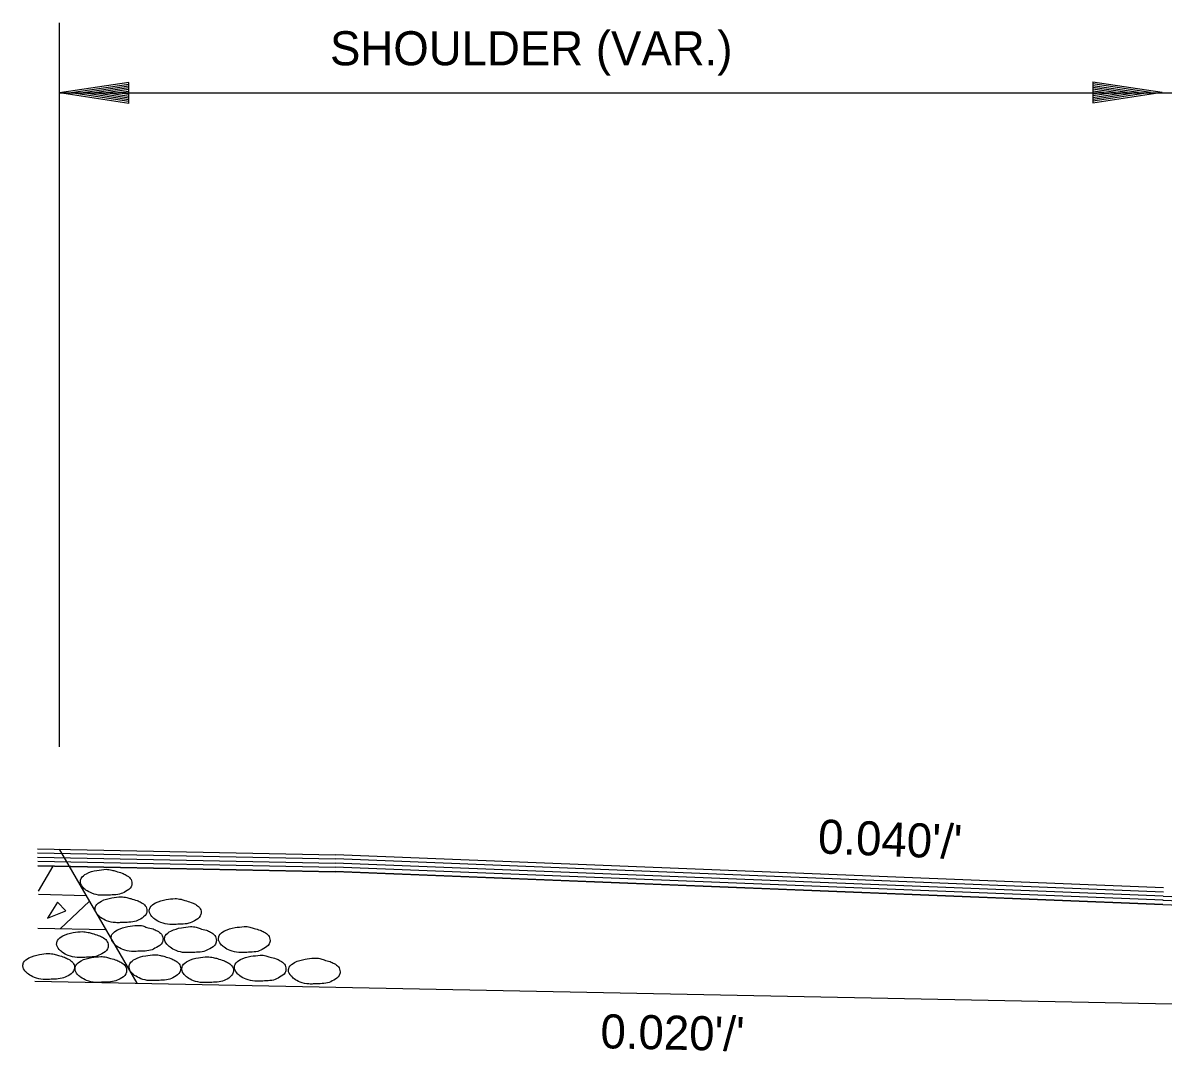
# Model space of a CAD drawing. Extents: x 1929624 to 1935547, y 596315 to 605721.
# Drawn here: x 1932754.9 to 1932958.2, y 604827.1 to 605010.5 of the extents above; entities that cross this region are included whole.
import ezdxf

# ---------------------------------------------------------------- set-up
doc = ezdxf.new("R2010")
doc.units = 0
doc.layers.add('Default', color=7, linetype='Continuous')

msp = doc.modelspace()

# ---------------------------------------------------------------- linework, layer by layer
at = {"layer": 'Default'}
for p, q in [((1932761.46, 604881.33), (1932761.46, 605010.47)), ((1932773.79, 604999.81), (1932761.46, 604997.97)), ((1932773.79, 604999.49), (1932763.53, 604997.97)), ((1932773.79, 604999.17), (1932765.65, 604997.97)), ((1932773.79, 604998.88), (1932767.71, 604997.97)), ((1932773.79, 604998.56), (1932769.78, 604997.97)), ((1932773.79, 604998.24), (1932771.85, 604997.97)), ((1932773.79, 604996.1), (1932773.79, 604999.81)), ((1932945.72, 604999.94), (1932958.05, 604998.07)), ((1932945.72, 604999.94), (1932945.72, 604996.22)), ((1932945.72, 604999.62), (1932955.98, 604998.07)), ((1932945.72, 604999.3), (1932953.87, 604998.07)), ((1932945.72, 604999), (1932951.8, 604998.07)), ((1932945.72, 604998.68), (1932949.73, 604998.07)), ((1932945.72, 604998.36), (1932947.67, 604998.07)), ((1932945.72, 604996.22), (1932958.05, 604998.07)), ((1932945.72, 604997.48), (1932949.73, 604998.07)), ((1932945.72, 604996.86), (1932953.87, 604998.07)), ((1932945.72, 604996.54), (1932955.98, 604998.07)), ((1932945.72, 604997.16), (1932951.8, 604998.07)), ((1932945.72, 604997.8), (1932947.67, 604998.07)), ((1932761.46, 604997.97), (1933091.99, 604997.97)), ((1932773.79, 604996.1), (1932761.46, 604997.97)), ((1932773.79, 604996.42), (1932763.53, 604997.97)), ((1932773.79, 604996.74), (1932765.65, 604997.97)), ((1932773.79, 604997.03), (1932767.71, 604997.97)), ((1932773.79, 604997.35), (1932769.78, 604997.97)), ((1932773.79, 604997.67), (1932771.85, 604997.97)), ((1932757.5, 604863.16), (1932810.67, 604862.11)), ((1932757.5, 604862.43), (1932810.67, 604861.37)), ((1932775.29, 604839.18), (1932761.46, 604863.08)), ((1932958.29, 604856.2), (1932810.67, 604862.11)), ((1932757.53, 604861.69), (1932810.67, 604860.63)), ((1932757.55, 604860.95), (1932810.67, 604859.89)), ((1932757.58, 604860.21), (1932810.62, 604859.15)), ((1932757.58, 604860.11), (1932810.67, 604859.06)), ((1932757.68, 604855.64), (1932760.33, 604860.09)), ((1932958.25, 604854.73), (1932810.62, 604860.63)), ((1932958.25, 604853.99), (1932810.62, 604859.89)), ((1932958.29, 604855.46), (1932810.67, 604861.37)), ((1932958.2, 604853.25), (1932810.57, 604859.15)), ((1932958.2, 604853.15), (1932810.67, 604859.06)), ((1932757.7, 604855.05), (1932766.21, 604854.87)), ((1932761.56, 604848.92), (1932766.8, 604853.86)), ((1932958.2, 604853.99), (1933092.85, 604848.6)), ((1932958.23, 604854.73), (1933092.89, 604849.34)), ((1932958.17, 604853.25), (1933092.83, 604847.86)), ((1932757.58, 604849), (1932769.75, 604848.75)), ((1932757.02, 604839.54), (1933150.4, 604831.72))]:
    msp.add_line(p, q, dxfattribs=at)
msp.add_lwpolyline([(1932759.31, 604850.78), (1932762.56, 604852.11), (1932761.08, 604853.68), (1932759.31, 604850.78)], dxfattribs=at)
for points in [[(1932769.74, 604859.51), (1932768.12, 604859.32), (1932766.25, 604858.73), (1932765.31, 604857.89), (1932765.16, 604857.3), (1932765.61, 604856.32), (1932766.15, 604855.82), (1932767.23, 604855.23), (1932768.8, 604854.89), (1932769.59, 604854.89), (1932770.82, 604854.94), (1932772.15, 604855.09), (1932773.23, 604855.53), (1932774.22, 604856.41), (1932774.37, 604857.01), (1932774.07, 604857.89), (1932773.33, 604858.48), (1932772.59, 604858.83), (1932771.51, 604859.17), (1932770.77, 604859.37), (1932769.74, 604859.51)], [(1932772.41, 604854.63), (1932770.79, 604854.43), (1932768.92, 604853.84), (1932767.94, 604853), (1932767.79, 604852.41), (1932768.23, 604851.43), (1932768.77, 604850.94), (1932769.85, 604850.35), (1932771.43, 604850), (1932772.27, 604850), (1932773.5, 604850.05), (1932774.82, 604850.2), (1932775.86, 604850.64), (1932776.89, 604851.53), (1932777.04, 604852.12), (1932776.74, 604853), (1932776.01, 604853.59), (1932775.27, 604853.94), (1932774.14, 604854.28), (1932773.45, 604854.48), (1932772.41, 604854.63)], [(1932782.07, 604854.31), (1932780.45, 604854.11), (1932778.58, 604853.52), (1932777.6, 604852.68), (1932777.45, 604852.09), (1932777.89, 604851.11), (1932778.43, 604850.62), (1932779.52, 604850.03), (1932781.09, 604849.68), (1932781.93, 604849.68), (1932783.16, 604849.73), (1932784.49, 604849.88), (1932785.52, 604850.32), (1932786.55, 604851.21), (1932786.7, 604851.8), (1932786.4, 604852.68), (1932785.67, 604853.27), (1932784.93, 604853.62), (1932783.8, 604853.96), (1932783.11, 604854.16), (1932782.07, 604854.31)], [(1932765.51, 604848.42), (1932763.88, 604848.22), (1932762.01, 604847.63), (1932761.08, 604846.79), (1932760.93, 604846.2), (1932761.37, 604845.22), (1932761.92, 604844.73), (1932763, 604844.14), (1932764.57, 604843.79), (1932765.36, 604843.79), (1932766.59, 604843.84), (1932767.92, 604843.99), (1932769, 604844.43), (1932769.99, 604845.32), (1932770.13, 604845.91), (1932769.84, 604846.79), (1932769.1, 604847.39), (1932768.36, 604847.73), (1932767.28, 604848.07), (1932766.54, 604848.27), (1932765.51, 604848.42)], [(1932775.28, 604849.51), (1932773.65, 604849.31), (1932771.78, 604848.72), (1932770.8, 604847.89), (1932770.65, 604847.34), (1932771.09, 604846.36), (1932771.63, 604845.82), (1932772.72, 604845.23), (1932774.29, 604844.88), (1932775.13, 604844.88), (1932776.36, 604844.93), (1932777.69, 604845.08), (1932778.72, 604845.57), (1932779.75, 604846.41), (1932779.9, 604847.05), (1932779.61, 604847.93), (1932778.87, 604848.53), (1932778.13, 604848.87), (1932777, 604849.16), (1932776.31, 604849.41), (1932775.28, 604849.51)], [(1932784.79, 604849.29), (1932783.17, 604849.09), (1932781.3, 604848.5), (1932780.31, 604847.66), (1932780.16, 604847.12), (1932780.61, 604846.14), (1932781.15, 604845.6), (1932782.23, 604845.01), (1932783.8, 604844.66), (1932784.64, 604844.66), (1932785.87, 604844.71), (1932787.2, 604844.86), (1932788.23, 604845.35), (1932789.27, 604846.19), (1932789.41, 604846.83), (1932789.12, 604847.71), (1932788.38, 604848.3), (1932787.64, 604848.65), (1932786.51, 604848.94), (1932785.82, 604849.19), (1932784.79, 604849.29)], [(1932794.37, 604849.3), (1932792.74, 604849.11), (1932790.87, 604848.52), (1932789.94, 604847.68), (1932789.79, 604847.14), (1932790.23, 604846.15), (1932790.78, 604845.61), (1932791.86, 604845.02), (1932793.43, 604844.68), (1932794.22, 604844.68), (1932795.45, 604844.73), (1932796.78, 604844.88), (1932797.86, 604845.37), (1932798.85, 604846.2), (1932798.99, 604846.84), (1932798.7, 604847.73), (1932797.96, 604848.32), (1932797.22, 604848.66), (1932796.14, 604848.96), (1932795.4, 604849.21), (1932794.37, 604849.3)], [(1932759.48, 604844.51), (1932757.86, 604844.31), (1932755.99, 604843.72), (1932755.05, 604842.88), (1932754.9, 604842.29), (1932755.35, 604841.31), (1932755.89, 604840.82), (1932756.97, 604840.23), (1932758.54, 604839.88), (1932759.33, 604839.88), (1932760.56, 604839.93), (1932761.89, 604840.08), (1932762.97, 604840.52), (1932763.96, 604841.41), (1932764.11, 604842), (1932763.81, 604842.88), (1932763.07, 604843.47), (1932762.33, 604843.82), (1932761.25, 604844.16), (1932760.51, 604844.36), (1932759.48, 604844.51)], [(1932768.79, 604843.97), (1932767.16, 604843.78), (1932765.29, 604843.19), (1932764.36, 604842.35), (1932764.21, 604841.76), (1932764.65, 604840.77), (1932765.2, 604840.28), (1932766.28, 604839.69), (1932767.85, 604839.35), (1932768.64, 604839.35), (1932769.87, 604839.4), (1932771.2, 604839.54), (1932772.28, 604839.99), (1932773.27, 604840.87), (1932773.41, 604841.46), (1932773.12, 604842.35), (1932772.38, 604842.94), (1932771.64, 604843.28), (1932770.56, 604843.63), (1932769.82, 604843.83), (1932768.79, 604843.97)], [(1932778.43, 604844.29), (1932776.81, 604844.1), (1932774.94, 604843.51), (1932774, 604842.67), (1932773.86, 604842.08), (1932774.3, 604841.09), (1932774.84, 604840.6), (1932775.92, 604840.01), (1932777.5, 604839.67), (1932778.29, 604839.67), (1932779.52, 604839.72), (1932780.84, 604839.86), (1932781.93, 604840.31), (1932782.91, 604841.19), (1932783.06, 604841.78), (1932782.76, 604842.67), (1932782.03, 604843.26), (1932781.29, 604843.6), (1932780.2, 604843.95), (1932779.47, 604844.15), (1932778.43, 604844.29)], [(1932787.83, 604843.93), (1932786.21, 604843.74), (1932784.34, 604843.15), (1932783.4, 604842.31), (1932783.26, 604841.72), (1932783.7, 604840.73), (1932784.24, 604840.24), (1932785.32, 604839.65), (1932786.9, 604839.31), (1932787.68, 604839.31), (1932788.91, 604839.36), (1932790.24, 604839.5), (1932791.33, 604839.95), (1932792.31, 604840.83), (1932792.46, 604841.42), (1932792.16, 604842.31), (1932791.42, 604842.9), (1932790.69, 604843.24), (1932789.6, 604843.59), (1932788.86, 604843.78), (1932787.83, 604843.93)], [(1932797.21, 604844.19), (1932795.58, 604844), (1932793.71, 604843.41), (1932792.78, 604842.57), (1932792.63, 604842.03), (1932793.07, 604841.05), (1932793.61, 604840.5), (1932794.7, 604839.91), (1932796.27, 604839.57), (1932797.06, 604839.57), (1932798.29, 604839.62), (1932799.62, 604839.77), (1932800.7, 604840.26), (1932801.68, 604841.09), (1932801.83, 604841.73), (1932801.54, 604842.62), (1932800.8, 604843.21), (1932800.06, 604843.56), (1932798.98, 604843.85), (1932798.24, 604844.1), (1932797.21, 604844.19)], [(1932806.85, 604843.69), (1932805.23, 604843.49), (1932803.36, 604842.9), (1932802.42, 604842.06), (1932802.27, 604841.52), (1932802.72, 604840.54), (1932803.26, 604840), (1932804.34, 604839.41), (1932805.92, 604839.06), (1932806.7, 604839.06), (1932807.93, 604839.11), (1932809.26, 604839.26), (1932810.34, 604839.75), (1932811.33, 604840.59), (1932811.48, 604841.23), (1932811.18, 604842.11), (1932810.44, 604842.7), (1932809.7, 604843.05), (1932808.62, 604843.34), (1932807.88, 604843.59), (1932806.85, 604843.69)]]:
    msp.add_spline(points, degree=3, dxfattribs=at)

# ---------------------------------------------------------------- texts
for s, rotation, p in [('SHOULDER (VAR.)', 360, (1932809.68, 605002.89)), ("0.040'/'", 357.7094, (1932896.61, 604862.36)), ("0.020'/'", 358.8537, (1932857.86, 604827.61))]:
    msp.add_text(s, height=6.075, rotation=rotation, dxfattribs=at).set_placement(p)

doc.saveas('drawing.dxf')
